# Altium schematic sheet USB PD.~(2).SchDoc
size A3; SheetNumber: 5; SheetTotal: 5
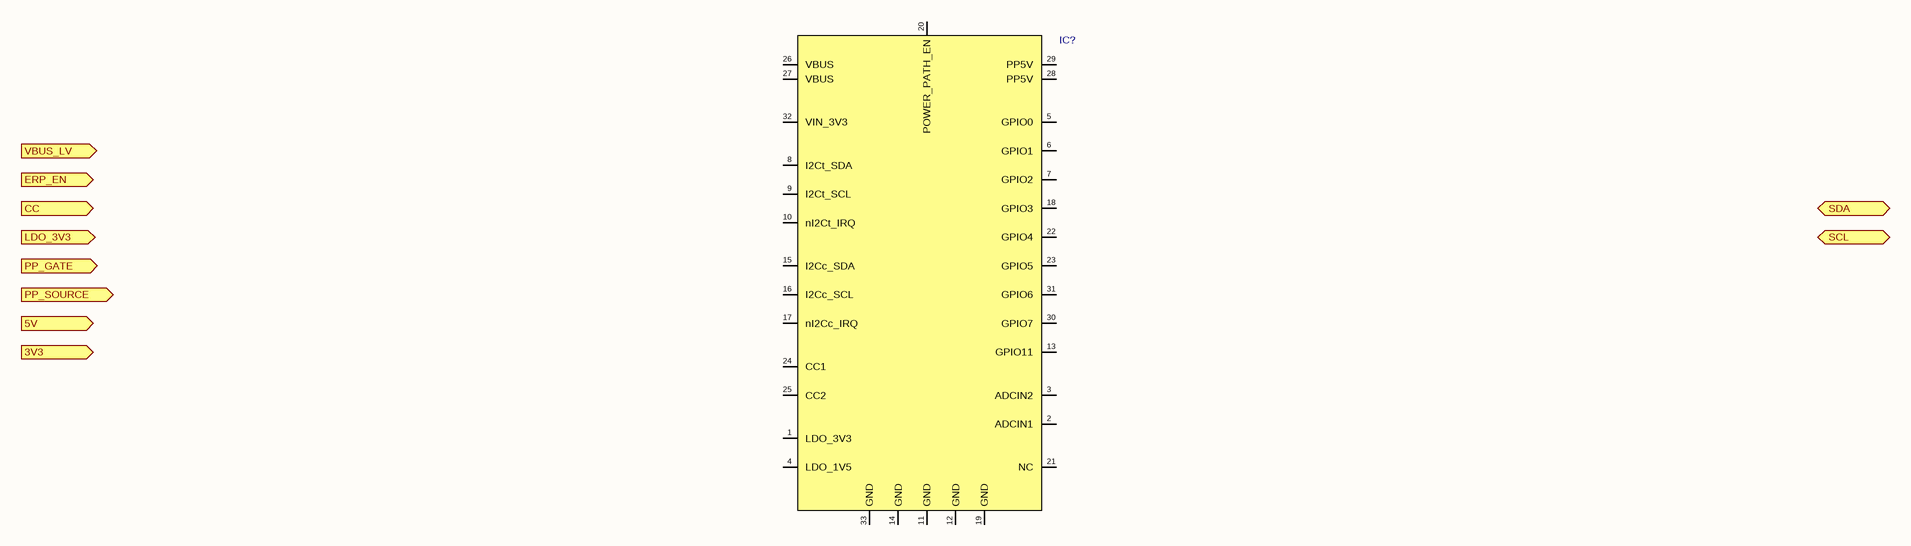
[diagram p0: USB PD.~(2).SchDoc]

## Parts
IC?  TPS26750SRSMR  [VQFN (32) 4x4]  (value not drawn)

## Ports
3V3 (in, see Arhitecture[3B], Power distribution[5D]), 5V (in, see Arhitecture[3B], Power distribution[5C]), CC (in, see Arhitecture[3B]), ERP_EN (in, see Arhitecture[3B]), LDO_3V3 (in, see Arhitecture[3B]), PP_GATE (out, see Arhitecture[4B]), PP_SOURCE (out, see Arhitecture[4B]), SCL (bidir, see Arhitecture[4B], Charger[3C]), SDA (bidir, see Arhitecture[4B], Charger[3C]), VBUS_LV (in, see Arhitecture[3B])

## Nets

Not connected (* = marked no-connect by the designer): IC? 1(LDO_3V3) 2(ADCIN1) 3(ADCIN2) 4(LDO_1V5) 5(GPIO0) 6(GPIO1) 7(GPIO2) 8(I2Ct_SDA) 9(I2Ct_SCL) 10(nI2Ct_IRQ) 11(GND) 12(GND) 13(GPIO11) 14(GND) 15(I2Cc_SDA) 16(I2Cc_SCL) 17(nI2Cc_IRQ) 18(GPIO3) 19(GND) 20(POWER_PATH_EN) 21(NC) 22(GPIO4) 23(GPIO5) 24(CC1) 25(CC2) 26(VBUS) 27(VBUS) 28(PP5V) 29(PP5V) 30(GPIO7) 31(GPIO6) 32(VIN_3V3) 33(GND)

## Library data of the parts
IC? = TPS26750SRSMR: USB PD IC EPR 240W; Manufacturer: Texas Instruments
